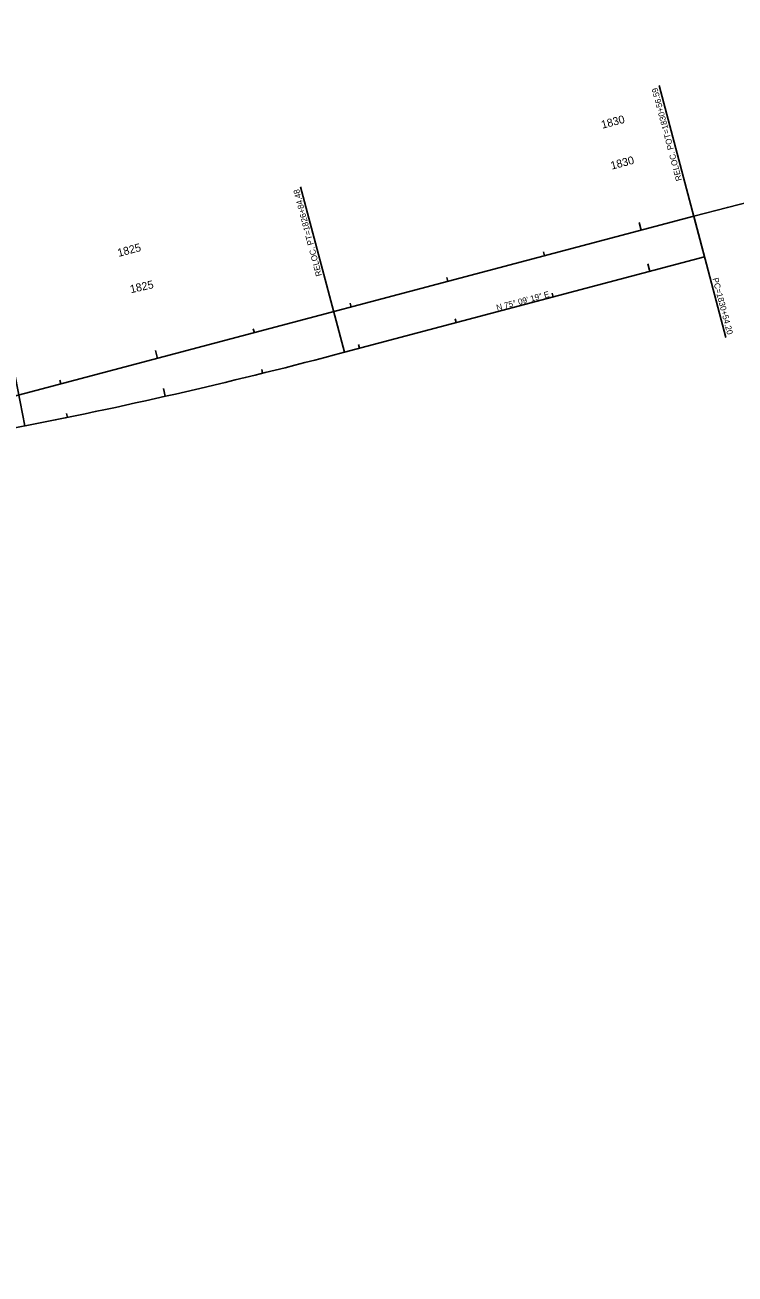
# Model space of a CAD drawing. Extents: x 2106154 to 2121963, y 864504 to 868517.
# Drawn here: x 2113410 to 2114119, y 867153 to 868401 of the extents above; entities that cross this region are included whole.
import ezdxf

# ---------------------------------------------------------------- set-up
doc = ezdxf.new("R2010")
doc.units = 0
for name, color, linetype in [('RD_HC_CL_Rel', 7, 'Continuous'), ('RD_HC_Data_Tic_Rel', 7, 'Continuous'), ('RD_HC_TX_Rel_Sta50', 7, 'Continuous'), ('RD_PD_EarthShd', 7, 'Continuous'), ('RD_PD_EOP', 7, 'Continuous'), ('RD_PD_Final_LnLine', 7, 'Continuous'), ('RD_Sketch1', 7, 'Continuous'), ('RD_Sketch10', 7, 'Continuous')]:
    doc.layers.add(name, color=color, linetype=linetype)

msp = doc.modelspace()

# ---------------------------------------------------------------- linework, layer by layer
at = {"layer": 'RD_HC_CL_Rel'}
msp.add_line((2114077.7, 868210), (2114109.9, 868088.7), dxfattribs=at)
at = {"layer": 'RD_HC_Data_Tic_Rel'}
for p, q in [((2113728.8, 868074.1), (2114088.5, 868169.4)), ((2113095.6, 867938.7), (2113409.5, 868000.5))]:
    msp.add_line(p, q, dxfattribs=at)
msp.add_arc((2112435, 872955.5), 5050, 281.1268, 284.8448, dxfattribs=at)
at = {"layer": 'RD_HC_TX_Rel_Sta50'}
for p, q in [((2114088.5, 868169.4), (2114043.1, 868340.7)), ((2113728.8, 868074.1), (2113684.9, 868239.4)), ((2113409.5, 868000.5), (2113376.4, 868169))]:
    msp.add_line(p, q, dxfattribs=at)
at = {"layer": 'RD_PD_EarthShd'}
for p, q in [((2114025.3, 868196.1), (2114023.3, 868203.9)), ((2113928.7, 868170.5), (2113927.6, 868174.4)), ((2113832, 868144.9), (2113831, 868148.7)), ((2113735.3, 868119.3), (2113734.3, 868123.1)), ((2113638.7, 868093.6), (2113637.6, 868097.5)), ((2113542, 868068), (2113540, 868075.8)), ((2113445.3, 868042.4), (2113444.3, 868046.3))]:
    msp.add_line(p, q, dxfattribs=at)
at = {"layer": 'RD_PD_EOP'}
msp.add_line((2110088.7, 867152.7), (2114077.7, 868210), dxfattribs=at)
msp.add_arc((2115545.6, 862671.7), 5729.6, 82.67967, 104.84478, dxfattribs=at)
at = {"layer": 'RD_Sketch1'}
for p, q in [((2114033.8, 868154.9), (2114031.7, 868162.6)), ((2113937.1, 868129.3), (2113936.1, 868133.2)), ((2113840.4, 868103.7), (2113839.4, 868107.5)), ((2113743.8, 868078.1), (2113742.8, 868081.9)), ((2113646.9, 868053.1), (2113646, 868057)), ((2113549.6, 868030.1), (2113547.9, 868037.9)), ((2113451.9, 868009), (2113451.1, 868012.9))]:
    msp.add_line(p, q, dxfattribs=at)

# ---------------------------------------------------------------- texts
at = {"layer": 'RD_HC_CL_Rel'}
msp.add_text('PC=1830+54.20', height=6, rotation=284.8448, dxfattribs=at).set_placement((2114096.3, 868147.7))
at = {"layer": 'RD_HC_TX_Rel_Sta50'}
for s, rotation, p in [('RELOC. POT=1830+56.59', 104.8448, (2114066, 868246.2)), ('RELOC. PT=1826+84.48', 104.8448, (2113706.3, 868150.9)), ('N 75%%d 09\' 19" E', 14.8448, (2113881.4, 868115.6))]:
    msp.add_text(s, height=6, rotation=rotation, dxfattribs=at).set_placement(p)
at = {"layer": 'RD_PD_Final_LnLine'}
for s, p in [('1830', (2113986.4, 868297.5)), ('1825', (2113503.1, 868169.4))]:
    msp.add_text(s, height=8, rotation=14.8448, dxfattribs=at).set_placement(p)
at = {"layer": 'RD_Sketch10'}
for s, rotation, p in [('1830', 14.8448, (2113995.8, 868256.6)), ('1825', 12.7517, (2113515.4, 868133.1))]:
    msp.add_text(s, height=8, rotation=rotation, dxfattribs=at).set_placement(p)

doc.saveas('drawing.dxf')
